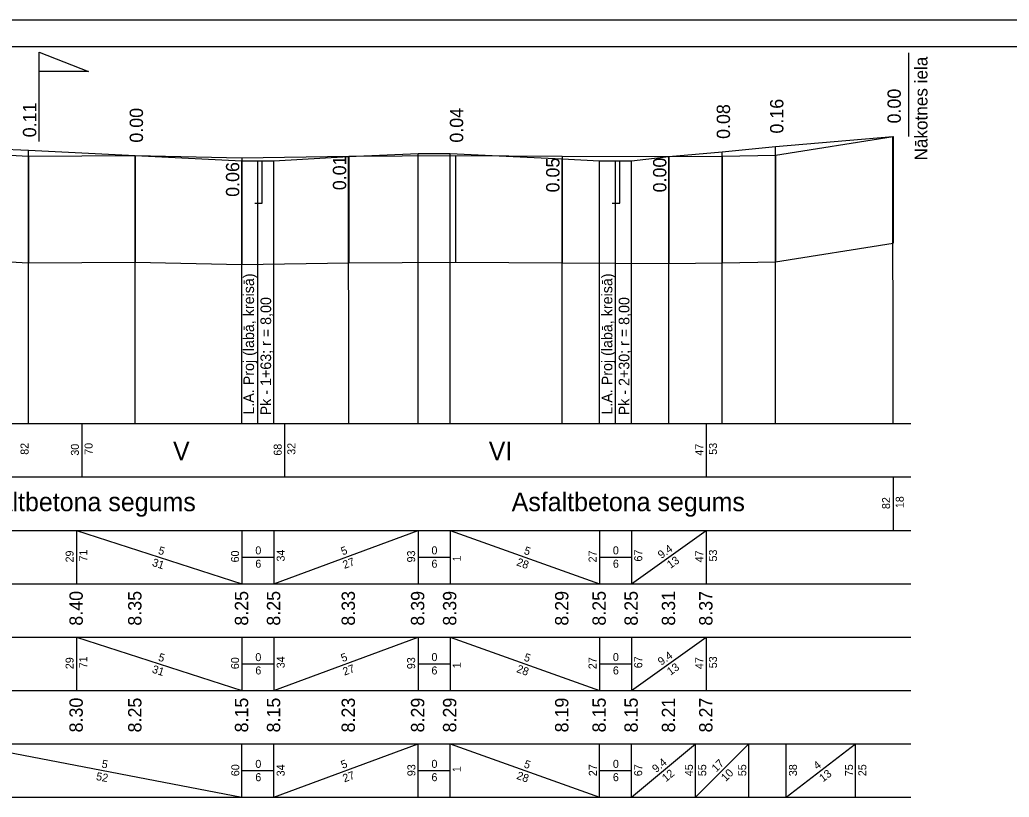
# Model space of a CAD drawing. Extents: x -465 to 136, y -149 to 148.
# Drawn here: x -221.2 to -35.8, y 2 to 147.7 of the extents above; entities that cross this region are included whole.
import ezdxf

# ---------------------------------------------------------------- set-up
doc = ezdxf.new("R2010")
doc.units = 0
for name, color, linetype in [('AA_Esosais_reljefs', 7, 'Continuous'), ('AA_Kritumi', 7, 'Continuous'), ('AA_M1000_A2', 7, 'Continuous'), ('AA_Nobrauktuves', 7, 'Continuous'), ('AA_Proj_gulijas', 7, 'Continuous'), ('AA_Projekta_atz', 7, 'Continuous'), ('AA_Projekta_linija', 7, 'Continuous'), ('AA_Ramis', 7, 'Continuous')]:
    doc.layers.add(name, color=color, linetype=linetype)

msp = doc.modelspace()

# ---------------------------------------------------------------- linework, layer by layer
at = {"layer": 'AA_Esosais_reljefs'}
for p, q in [((-79.59, 122.34), (-57.59, 125.84)), ((-57.59, 125.84), (-57.59, 105.84)), ((-239.59, 123.24), (-219.59, 122.14)), ((-219.59, 122.14), (-199.59, 122.24)), ((-219.59, 122.14), (-219.59, 102.14)), ((-199.59, 122.24), (-179.59, 121.84)), ((-199.59, 122.24), (-199.59, 102.24)), ((-179.59, 121.84), (-159.59, 122.14)), ((-179.59, 121.84), (-179.59, 101.84)), ((-159.59, 122.14), (-139.59, 122.24)), ((-159.59, 122.14), (-159.59, 102.14)), ((-139.59, 122.24), (-119.59, 122.14)), ((-139.59, 122.24), (-139.59, 102.24)), ((-119.59, 122.14), (-99.59, 122.04)), ((-119.59, 122.14), (-119.59, 102.14)), ((-99.59, 122.04), (-89.59, 122.14)), ((-99.59, 122.04), (-99.59, 102.04)), ((-89.59, 122.14), (-79.59, 122.34)), ((-89.59, 122.14), (-89.59, 102.14)), ((-79.59, 122.34), (-79.59, 102.34)), ((-79.59, 102.34), (-57.59, 105.84)), ((-239.59, 103.24), (-219.59, 102.14)), ((-219.59, 102.14), (-199.59, 102.24)), ((-199.59, 102.24), (-179.59, 101.84)), ((-179.59, 101.84), (-159.59, 102.14)), ((-159.59, 102.14), (-139.59, 102.24)), ((-139.59, 102.24), (-119.59, 102.14)), ((-119.59, 102.14), (-99.59, 102.04)), ((-99.59, 102.04), (-89.59, 102.14)), ((-89.59, 102.14), (-79.59, 102.34))]:
    msp.add_line(p, q, dxfattribs=at)
at = {"layer": 'AA_M1000_A2'}
for p, q in [((-464.59, 147.68), (135.72, 147.68)), ((-444.59, 142.68), (130.72, 142.68))]:
    msp.add_line(p, q, dxfattribs=at)
at = {"layer": 'AA_Nobrauktuves'}
for p, q in [((-217.59, 124.89), (-217.59, 141.61)), ((-54.6, 125.84), (-54.6, 141.46))]:
    msp.add_line(p, q, dxfattribs=at)
at = {"layer": 'AA_Proj_gulijas'}
for p, q in [((-176.6, 113.3), (-176.6, 121.24)), ((-176.6, 72.02), (-176.6, 121.24)), ((-175.8, 113.3), (-175.8, 121.24)), ((-109.6, 113.3), (-109.6, 121.24)), ((-109.6, 72.02), (-109.6, 121.24)), ((-108.8, 113.3), (-108.8, 121.24)), ((-177.2, 113.3), (-175.8, 113.3)), ((-110.2, 113.3), (-108.8, 113.3))]:
    msp.add_line(p, q, dxfattribs=at)
at = {"layer": 'AA_Projekta_linija'}
for p, q in [((-239.6, 124.24), (-219.6, 123.24)), ((-79.6, 123.94), (-57.6, 125.84)), ((-57.59, 72.02), (-57.6, 125.84)), ((-219.6, 123.24), (-199.6, 122.24)), ((-219.59, 72.02), (-219.6, 123.24)), ((-159.6, 122.04), (-146.6, 122.64)), ((-146.6, 122.64), (-140.6, 122.64)), ((-146.59, 72.02), (-146.6, 122.64)), ((-140.6, 122.64), (-119.6, 121.64)), ((-140.59, 72.02), (-140.6, 122.64)), ((-99.6, 122.04), (-89.6, 122.94)), ((-89.6, 122.94), (-79.6, 123.94)), ((-89.59, 72.02), (-89.6, 122.94)), ((-79.59, 72.02), (-79.6, 123.94)), ((-199.6, 122.24), (-179.6, 121.24)), ((-199.59, 72.02), (-199.6, 122.24)), ((-179.6, 121.24), (-173.6, 121.24)), ((-179.59, 72.02), (-179.6, 121.24)), ((-173.6, 121.24), (-159.6, 122.04)), ((-173.59, 72.02), (-173.6, 121.24)), ((-159.59, 72.02), (-159.6, 122.04)), ((-119.6, 121.64), (-112.6, 121.24)), ((-119.59, 72.02), (-119.6, 121.64)), ((-112.6, 121.24), (-106.6, 121.24)), ((-112.59, 72.02), (-112.6, 121.24)), ((-106.6, 121.24), (-99.6, 122.04)), ((-106.59, 72.02), (-106.6, 121.24)), ((-99.59, 72.02), (-99.6, 122.04))]:
    msp.add_line(p, q, dxfattribs=at)
at = {"layer": 'AA_Ramis'}
for p, q in [((-217.59, 141.61), (-208.32, 137.98)), ((-208.32, 137.98), (-217.59, 137.98)), ((-349.6, 72.02), (-54.28, 72.02)), ((-209.59, 72.02), (-209.59, 62.02)), ((-171.59, 72.02), (-171.59, 62.02)), ((-92.59, 72.02), (-92.59, 62.02)), ((-349.6, 62.02), (-54.28, 62.02)), ((-57.59, 62.02), (-57.59, 52.02)), ((-349.6, 52.02), (-54.28, 52.02)), ((-210.59, 52.02), (-210.59, 42.02)), ((-210.59, 52.02), (-179.59, 42.02)), ((-179.59, 52.02), (-179.59, 42.02)), ((-173.59, 52.02), (-173.59, 42.02)), ((-173.59, 42.02), (-146.59, 52.02)), ((-146.59, 52.02), (-146.59, 42.02)), ((-140.59, 52.02), (-140.59, 42.02)), ((-140.59, 52.02), (-112.59, 42.02)), ((-112.59, 52.02), (-112.59, 42.02)), ((-106.59, 52.02), (-106.59, 42.02)), ((-106.59, 42.02), (-92.59, 52.02)), ((-92.59, 52.02), (-92.59, 42.02)), ((-179.59, 47.02), (-173.59, 47.02)), ((-146.59, 47.02), (-140.59, 47.02)), ((-112.59, 47.02), (-106.59, 47.02)), ((-349.6, 42.02), (-54.28, 42.02)), ((-349.6, 32.02), (-54.28, 32.02)), ((-210.59, 32.02), (-210.59, 22.02)), ((-210.59, 32.02), (-179.59, 22.02)), ((-179.59, 32.02), (-179.59, 22.02)), ((-173.59, 32.02), (-173.59, 22.02)), ((-173.59, 22.02), (-146.59, 32.02)), ((-146.59, 32.02), (-146.59, 22.02)), ((-140.59, 32.02), (-140.59, 22.02)), ((-140.59, 32.02), (-112.59, 22.02)), ((-112.59, 32.02), (-112.59, 22.02)), ((-106.59, 32.02), (-106.59, 22.02)), ((-106.59, 22.02), (-92.59, 32.02)), ((-92.59, 32.02), (-92.59, 22.02)), ((-179.59, 27.02), (-173.59, 27.02)), ((-146.59, 27.02), (-140.59, 27.02)), ((-112.59, 27.02), (-106.59, 27.02)), ((-349.6, 22.02), (-54.28, 22.02)), ((-349.6, 12.02), (-54.28, 12.02)), ((-231.59, 12.02), (-179.59, 2.02)), ((-179.59, 2.02), (-179.59, 12.02)), ((-173.59, 2.02), (-173.59, 12.02)), ((-173.59, 2.02), (-146.59, 12.02)), ((-146.59, 2.02), (-146.59, 12.02)), ((-140.59, 2.02), (-140.59, 12.02)), ((-140.59, 12.02), (-112.59, 2.02)), ((-112.59, 2.02), (-112.59, 12.02)), ((-106.59, 2.02), (-106.59, 12.02)), ((-106.59, 2.02), (-94.59, 12.02)), ((-94.59, 2.02), (-94.59, 12.02)), ((-94.59, 2.02), (-84.59, 12.02)), ((-84.59, 2.02), (-84.59, 12.02)), ((-77.59, 2.02), (-77.59, 12.02)), ((-77.59, 2.02), (-64.59, 12.02)), ((-64.59, 2.02), (-64.59, 12.02)), ((-179.59, 7.02), (-173.59, 7.02)), ((-146.59, 7.02), (-140.59, 7.02)), ((-112.59, 7.02), (-106.59, 7.02)), ((-349.6, 2.02), (-54.28, 2.02))]:
    msp.add_line(p, q, dxfattribs=at)

# ---------------------------------------------------------------- texts
at = {"layer": 'AA_Kritumi'}
for s, rotation, p in [('82', 90, (-219.58, 66.18)), ('30', 90, (-210.14, 66.01)), ('70', 90, (-207.58, 66.18)), ('68', 90, (-172.14, 66.01)), ('32', 90, (-169.58, 66.18)), ('47', 90, (-93.14, 66.01)), ('53', 90, (-90.58, 66.18)), ('82', 90, (-58.14, 56.01)), ('18', 90, (-55.58, 56.18)), ('71', 90, (-208.58, 46.18)), ('5', 342.1213, (-195.4, 47.65)), ('34', 90, (-171.58, 46.18)), ('5', 20.3231, (-160.72, 47.32)), ('5', 340.3462, (-126.88, 47.65)), ('67', 90, (-104.58, 46.18)), ('9.4', 35.5377, (-101, 46.63)), ('53', 90, (-90.58, 46.18)), ('29', 90, (-211.14, 46.01)), ('31', 342.1213, (-196.55, 45.39)), ('60', 90, (-180.14, 46.01)), ('27', 20.3231, (-160.39, 44.78)), ('93', 90, (-147.14, 46.01)), ('1', 90, (-138.58, 46.18)), ('28', 340.3462, (-128.26, 45.49)), ('27', 90, (-113.14, 46.01)), ('13', 35.5377, (-99.29, 44.78)), ('47', 90, (-93.14, 46.01)), ('29', 90, (-211.14, 26.01)), ('71', 90, (-208.58, 26.18)), ('5', 342.1213, (-195.4, 27.65)), ('60', 90, (-180.14, 26.01)), ('34', 90, (-171.58, 26.18)), ('5', 20.3231, (-160.72, 27.32)), ('93', 90, (-147.14, 26.01)), ('5', 340.3462, (-126.88, 27.65)), ('27', 90, (-113.14, 26.01)), ('67', 90, (-104.58, 26.18)), ('9.4', 35.5377, (-101, 26.63)), ('47', 90, (-93.14, 26.01)), ('53', 90, (-90.58, 26.18)), ('31', 342.1213, (-196.55, 25.39)), ('27', 20.3231, (-160.39, 24.78)), ('1', 90, (-138.58, 26.18)), ('28', 340.3462, (-128.26, 25.49)), ('13', 35.5377, (-99.29, 24.78)), ('9.4', 39.8056, (-101.97, 6.53)), ('5', 349.1145, (-205.97, 7.6)), ('60', 90, (-180.09, 5.96)), ('34', 90, (-171.59, 5.93)), ('5', 20.3231, (-160.72, 7.32)), ('93', 90, (-147.09, 5.96)), ('1', 90, (-138.59, 6.71)), ('5', 340.3462, (-126.88, 7.65)), ('27', 90, (-113.09, 5.96)), ('67', 90, (-104.59, 5.96)), ('45', 90, (-95.09, 5.96)), ('55', 90, (-92.59, 5.96)), ('17', 45, (-90.69, 6.63)), ('55', 90, (-85.09, 5.96)), ('38', 90, (-75.59, 5.96)), ('4', 37.5686, (-71.8, 7.1)), ('75', 90, (-65.09, 5.96)), ('25', 90, (-62.59, 5.96)), ('52', 349.1145, (-207.01, 5.26)), ('27', 20.3231, (-160.39, 4.78)), ('28', 340.3462, (-128.26, 5.49)), ('12', 39.8056, (-100.12, 4.81)), ('10', 45, (-88.93, 4.86)), ('13', 37.5686, (-70.71, 4.79))]:
    msp.add_text(s, height=1.5, rotation=rotation, dxfattribs=at).set_placement(p)
for s, p in [('0', (-177.08, 47.52)), ('0', (-144.08, 47.52)), ('0', (-110.08, 47.52)), ('6', (-177.08, 45.02)), ('6', (-144.08, 45.02)), ('6', (-110.08, 45.02)), ('0', (-177.08, 27.52)), ('0', (-144.08, 27.52)), ('0', (-110.08, 27.52)), ('6', (-177.08, 25.02)), ('6', (-144.08, 25.02)), ('6', (-110.08, 25.02)), ('0', (-177.08, 7.52)), ('0', (-144.08, 7.52)), ('0', (-110.08, 7.52)), ('6', (-177.08, 5.02)), ('6', (-144.08, 5.02)), ('6', (-110.08, 5.02))]:
    msp.add_text(s, height=1.5, dxfattribs=at).set_placement(p)
at = {"layer": 'AA_Nobrauktuves'}
msp.add_text('Nākotnes iela', height=2.4, rotation=90, dxfattribs=at).set_placement((-51.13, 121.32))
at = {"layer": 'AA_Proj_gulijas'}
for s, p in [('L.A. Proj (labā, kreisā)', (-177.32, 73.7)), ('L.A. Proj (labā, kreisā)', (-110.18, 73.7)), ('Pk - 1+63; r = 8,00', (-174.12, 73.57)), ('Pk - 2+30; r = 8,00', (-106.99, 73.57))]:
    msp.add_text(s, height=2, rotation=90, dxfattribs=at).set_placement(p)
at = {"layer": 'AA_Projekta_atz'}
for s, p in [('0.00', (-56.13, 128.26)), ('0.11', (-218.13, 125.66)), ('0.08', (-88.13, 125.36)), ('0.16', (-78.13, 126.36)), ('0.00', (-198.13, 124.66)), ('0.04', (-138.13, 124.66)), ('0.06', (-180.09, 114.51)), ('0.01', (-160.06, 115.75)), ('0.05', (-120.09, 115.34)), ('0.00', (-100.06, 115.34)), ('8.40', (-209.42, 34.16)), ('8.35', (-198.42, 34.16)), ('8.25', (-178.42, 34.16)), ('8.25', (-172.42, 34.16)), ('8.33', (-158.42, 34.16)), ('8.39', (-145.42, 34.16)), ('8.39', (-139.42, 34.16)), ('8.29', (-118.42, 34.16)), ('8.25', (-111.42, 34.16)), ('8.25', (-105.42, 34.16)), ('8.31', (-98.42, 34.16)), ('8.37', (-91.42, 34.16)), ('8.30', (-209.42, 14.16)), ('8.25', (-198.42, 14.16)), ('8.15', (-178.42, 14.16)), ('8.15', (-172.42, 14.16)), ('8.23', (-158.42, 14.16)), ('8.29', (-145.42, 14.16)), ('8.29', (-139.42, 14.16)), ('8.19', (-118.42, 14.16)), ('8.15', (-111.42, 14.16)), ('8.15', (-105.42, 14.16)), ('8.21', (-98.42, 14.16)), ('8.27', (-91.42, 14.16))]:
    msp.add_text(s, height=2.5, rotation=90, dxfattribs=at).set_placement(p)
at = {"layer": 'AA_Ramis'}
for s, p in [('V', (-192.51, 65.16)), ('VI', (-133.34, 65.16)), ('Asfaltbetona segums', (-231.95, 55.61)), ('Asfaltbetona segums', (-129.05, 55.61))]:
    msp.add_text(s, height=3.5, dxfattribs=at).set_placement(p)

doc.saveas('drawing.dxf')
